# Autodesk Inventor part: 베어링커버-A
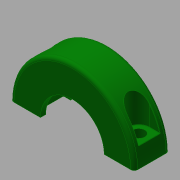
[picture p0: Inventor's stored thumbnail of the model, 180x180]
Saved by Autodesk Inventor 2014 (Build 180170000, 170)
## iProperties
Created: 2018-01
Part Number: 베어링커버-A
Material: 일반
Document SubType Name: Modeling
Designer: mduedu
Density: 1 g/cm^3
Appearance: 진녹색
Mass: 2.66163 g
Surface Area: 19.9383 cm^2
Volume: 2.66163 cm^3
Author: mduedu
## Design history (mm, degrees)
sketch "스케치1"
  geometry: L1 (-17.5, 0)-(17.5, 0); A1 r 17.5 centre (0, 0) between (-17.5, 0) and (17.5, 0); 2 further points
  constraints: 2 coincident, 2 end point, 2 point on circle, 1 centre point, 1 horizontal, 1 midpoint
  dimensions: "d0" = 35 diameter of A1
extrude "돌출1" new body sketch "스케치1" stored distance "d1" = 10; taper "d2" = 0 deg
sketch "스케치2"
  geometry: C1 r 11 at (0, 0); C2 r 9 at (0, 0); 1 further point
  constraints: 2 centre point, 2 coincident
  dimensions: "d3" = 22 diameter of C1; "d4" = 18 diameter of C2
extrude "돌출2" cut sketch "스케치2" stored distance "d5" = 7; taper "d6" = 0 deg
extrude "돌출3" cut sketch "스케치2" stored distance "d7" = 7; taper "d8" = 0 deg
fillet "모깎기1" dims "d9" = 0.3
fillet "모깎기2" dims "d10" = 1
node "작업 평면1"
sketch "스케치3"
  geometry: L1 (-15.5, -3.5)-(33.5, -3.5) reference; L2 (-4.771, -6.5)-(-7.771, -6.5); L3 (-7.771, -6.5)-(-7.771, -0.5); L4 (-7.771, -0.5)-(-4.771, -0.5); L5 (-0.46, -7)-(1.517, -7) reference; L6 (1.517, -7)-(1.517, -8.5) reference; L7 (1.517, -8.5)-(-6.724, -8.5) reference; L8 (-7.771, -7.5)-(-7.771, 0.5) reference; L9 (-6.724, 1.5)-(1.517, 1.5) reference; L10 (1.517, 1.5)-(1.517, 0) reference; L11 (1.517, 0)-(-0.46, 0) reference; L12 (-0.798, -0.3)-(-0.798, -6.7) reference; L13 (18.798, -6.7)-(18.798, -0.3) reference; L14 (18.46, 0)-(16.483, 0) reference; L15 (16.483, 0)-(16.483, 1.5) reference; L16 (16.483, 1.5)-(24.724, 1.5) reference; L17 (25.771, 0.5)-(25.771, -7.5) reference; L18 (24.724, -8.5)-(16.483, -8.5) reference; L19 (16.483, -8.5)-(16.483, -7) reference; L20 (16.483, -7)-(18.46, -7) reference; A1 r 3 centre (-4.771, -3.5) between (-4.771, -6.5) and (-4.771, -0.5); 1 further point
  constraints: 6 end point, 2 point on circle, 2 tangent, 1 centre point, 1 collinear, 1 horizontal, 1 parallel, 1 perpendicular, 1 point on line, 8 other
  dimensions: "d12" = 6 distance between parallel lines of L4 L2; "d14" = 6 dimension on A1 L3
extrude "돌출4" cut sketch "스케치3" stored distance "d15" = 0; taper "d16" = 0 deg
sketch "스케치4"
  geometry: 7 further points
  constraints: 4 vertical alignment, 2 horizontal alignment
sketch "스케치5"
  geometry: 2 further points
  constraints: 2 other
hole "구멍1" sketch "스케치5" at (-22.771, 3.5), (4.771, 3.5) diameter "d17" = 3.4; stored, may be unused: countersink angle "d21" = 90 deg, drill point angle "d23" = 0 deg; dims "d18" = 6, "d19" = 4, "d20" = 2, "d22" = 8
fillet "모깎기3" dims "d24" = 0.1
node "솔리드1"
mirror "대칭1"
node "절단 모서리 투영1"
other parameters: "d11" = -5
